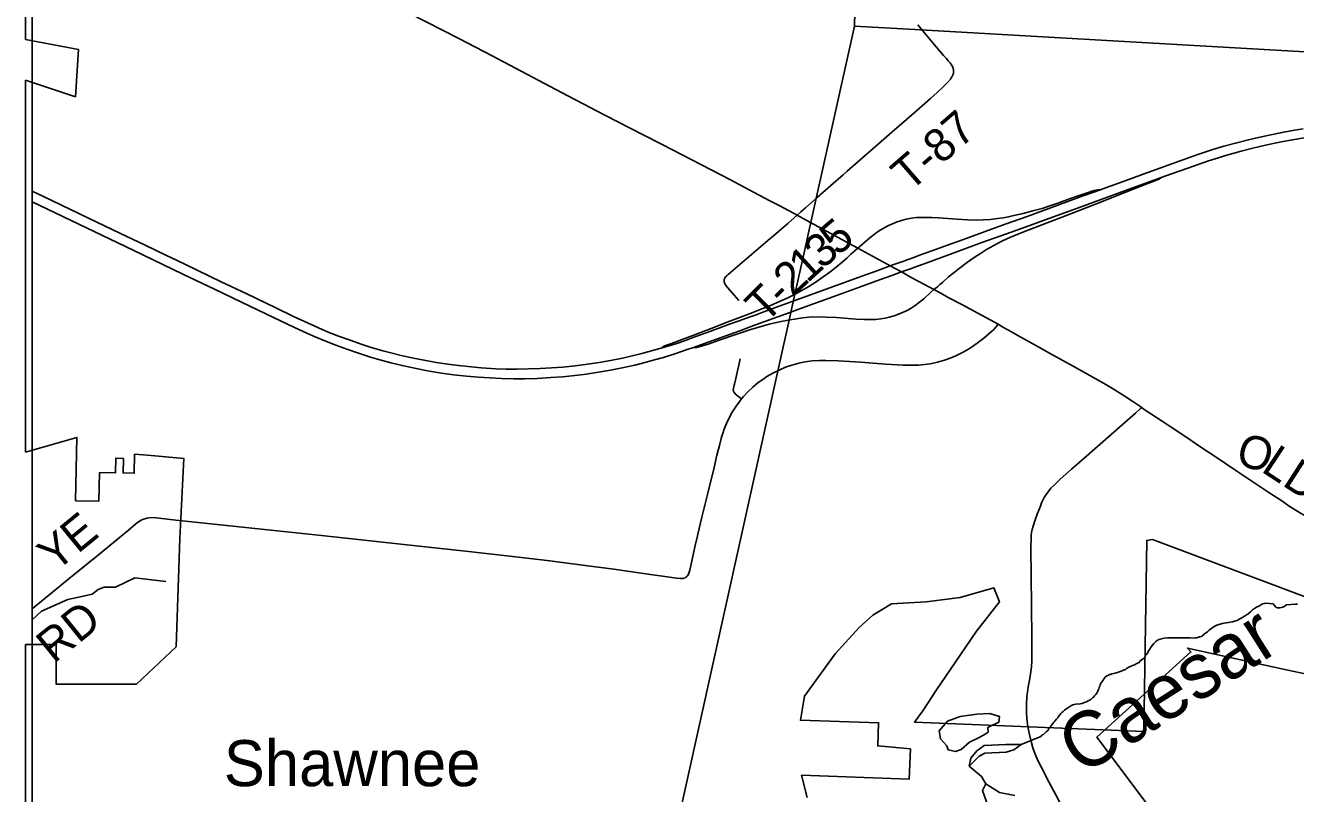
# Model space of a CAD drawing. Extents: x -5.4 to 49.9, y 13.2 to 48.4.
# Drawn here: x 26.266 to 28.445, y 43.526 to 44.845 of the extents above; entities that cross this region are included whole.
import ezdxf

# ---------------------------------------------------------------- set-up
doc = ezdxf.new("R2010")
doc.units = 0
for name, color, linetype in [('GM_X_Corporation', 7, 'Continuous'), ('GM_X_County_Road', 7, 'Continuous'), ('GM_X_County_Road_Text', 7, 'Continuous'), ('GM_X_Interchange_Ramps', 7, 'Continuous'), ('GM_X_Major_Lake', 7, 'Continuous'), ('GM_X_Major_River', 7, 'Continuous'), ('GM_X_Major_River_Text', 7, 'Continuous'), ('GM_X_Minor_Lake', 7, 'Continuous'), ('GM_X_Minor_River', 7, 'Continuous'), ('GM_X_Township', 7, 'Continuous'), ('GM_X_Township_Road', 7, 'Continuous'), ('GM_X_Township_Road_Text', 7, 'Continuous'), ('GM_X_Unincorporated_Text', 7, 'Continuous'), ('GM_X_US_Route', 7, 'Continuous')]:
    doc.layers.add(name, color=color, linetype=linetype)

msp = doc.modelspace()

# ---------------------------------------------------------------- linework, layer by layer
at = {"layer": 'GM_X_Corporation'}
for p, q in [((26.2655, 44.9666), (26.2655, 44.8206)), ((26.2655, 44.7507), (26.2655, 44.1125)), ((26.2655, 43.7825), (26.2655, 42.0542))]:
    msp.add_line(p, q, dxfattribs=at)
for points in [[(26.2655, 44.8206), (26.3566, 44.8036), (26.3514, 44.7225), (26.2655, 44.7507)], [(26.2655, 44.1125), (26.354, 44.1377), (26.3517, 44.0289), (26.3915, 44.0281), (26.3925, 44.0775), (26.42, 44.0769), (26.4205, 44.1021), (26.4337, 44.1015), (26.4332, 44.0767), (26.4522, 44.0763), (26.4528, 44.1087), (26.4815, 44.1066), (26.5373, 44.1017), (26.5303, 43.9641), (26.5283, 43.896), (26.524, 43.7782), (26.4559, 43.714), (26.3185, 43.714), (26.3185, 43.7825), (26.2655, 43.7825)], [(27.607, 43.5196), (27.5973, 43.558), (27.7819, 43.5513), (27.784, 43.6031), (27.7279, 43.6084), (27.7293, 43.6479), (27.5954, 43.6522), (27.6024, 43.6936), (27.6548, 43.7665), (27.6959, 43.8117), (27.7194, 43.8326), (27.7513, 43.8519), (27.8109, 43.8557), (27.8694, 43.8629), (27.9272, 43.8793), (27.9368, 43.8557), (27.8973, 43.805), (27.8693, 43.7642), (27.8286, 43.7043), (27.8052, 43.6682), (27.7912, 43.6491), (28.1844, 43.6332), (28.1896, 43.961), (28.1991, 43.9624), (28.4932, 43.852)], [(28.4935, 43.3784), (28.4313, 43.404), (28.3949, 43.0628), (28.0147, 43.1011), (28.0164, 43.1218), (28.0232, 43.1917), (28.0637, 43.1878), (28.081, 43.3697), (28.1405, 43.3662), (28.1461, 43.4292), (28.1296, 43.4307), (28.1348, 43.4852), (28.2128, 43.4782), (28.2091, 43.4829), (28.104, 43.6235), (28.2652, 43.7695), (28.2592, 43.7763), (28.4317, 43.7385), (28.475, 43.729)]]:
    msp.add_lwpolyline(points, dxfattribs=at)
at = {"layer": 'GM_X_County_Road'}
for points in [[(26.8947, 44.8808), (26.925, 44.8655), (27.009, 44.8225), (27.0663, 44.7925), (27.196, 44.7242), (27.2235, 44.7097), (27.2445, 44.6989), (27.2809, 44.68), (27.3256, 44.6569), (27.3583, 44.6402), (27.4753, 44.5798), (27.506, 44.5634), (27.543, 44.544)], [(27.543, 44.544), (27.5533, 44.5386), (27.5598, 44.5351)], [(27.5598, 44.5351), (27.5897, 44.5192)], [(27.5897, 44.5192), (27.6054, 44.5106), (27.6399, 44.4918), (27.6788, 44.4706), (27.6939, 44.4627)], [(27.6939, 44.4627), (27.7252, 44.4454), (27.7495, 44.4321), (27.7687, 44.4217), (27.7867, 44.4118), (27.8079, 44.4003), (27.8244, 44.3913)], [(27.8244, 44.3913), (27.8361, 44.385), (27.8489, 44.378), (27.872, 44.3656), (27.9343, 44.3318)], [(27.9343, 44.3318), (27.9424, 44.3272), (27.951, 44.3225), (27.9736, 44.3098), (27.9887, 44.3013), (28.0001, 44.2949), (28.0268, 44.28)], [(28.0268, 44.28), (28.0343, 44.2759), (28.063, 44.2599), (28.1012, 44.239), (28.119, 44.2288), (28.1338, 44.2197), (28.1506, 44.209), (28.1657, 44.1992), (28.1808, 44.189)], [(27.9918, 43.842), (27.9917, 43.8506), (27.9911, 43.8985), (27.9908, 43.9501), (27.9912, 43.9637), (27.9914, 43.9699), (27.992, 43.9747), (27.993, 43.9796), (27.9947, 43.9855), (27.998, 43.9961), (28.0016, 44.0061), (28.007, 44.02), (28.0091, 44.0253), (28.0118, 44.0309), (28.0136, 44.0345), (28.0157, 44.0383), (28.0186, 44.0423), (28.022, 44.0468), (28.0251, 44.0505), (28.03, 44.0552), (28.0411, 44.066), (28.0606, 44.0831), (28.0817, 44.1016), (28.1475, 44.1595), (28.1699, 44.1793), (28.179, 44.1874), (28.1808, 44.189)], [(28.1808, 44.189), (28.1852, 44.1859), (28.2157, 44.1656), (28.2282, 44.1574), (28.258, 44.1373), (28.2747, 44.1264), (28.2876, 44.1178), (28.3066, 44.1051), (28.3421, 44.0812), (28.3992, 44.0433), (28.4212, 44.0287), (28.4273, 44.0244), (28.434, 44.02), (28.4398, 44.0163), (28.4533, 44.0077), (28.4613, 44.0029), (28.4753, 43.995), (28.4933, 43.9852), (28.5266, 43.9671), (28.5415, 43.9591)], [(27.9838, 43.6938), (27.9847, 43.7003), (27.986, 43.7095), (27.9888, 43.7241), (27.9906, 43.7358), (27.9915, 43.7439), (27.9921, 43.7538), (27.9924, 43.7619), (27.9924, 43.7688), (27.9925, 43.8003), (27.9918, 43.842)], [(28.0483, 43.4917), (28.0473, 43.4956), (28.0453, 43.5009), (28.0407, 43.5099), (28.0339, 43.5231), (28.022, 43.5457), (28.0088, 43.571), (28.0023, 43.5844), (27.9982, 43.5941), (27.9943, 43.6051), (27.9904, 43.6182), (27.9875, 43.6302), (27.9855, 43.6418), (27.9839, 43.6547), (27.983, 43.667), (27.9829, 43.6788), (27.9837, 43.693), (27.9838, 43.6938)]]:
    msp.add_lwpolyline(points, dxfattribs=at)
at = {"layer": 'GM_X_Interchange_Ramps'}
for points in [[(27.8244, 44.3913), (27.8302, 44.3964), (27.8344, 44.4), (27.8394, 44.4043), (27.8494, 44.4132), (27.8568, 44.4193), (27.8676, 44.4277), (27.8821, 44.4384), (27.8933, 44.4463), (27.9042, 44.4535), (27.9148, 44.46), (27.9272, 44.4671), (27.9399, 44.4737), (27.9505, 44.4789), (27.9612, 44.4838), (27.9768, 44.4902), (28.011, 44.5033), (28.05, 44.5182), (28.1015, 44.5383), (28.1517, 44.5578), (28.1735, 44.5664), (28.1987, 44.5762), (28.2093, 44.5803), (28.2109, 44.5811), (28.2141, 44.5835)], [(28.1101, 44.5629), (28.1053, 44.5625), (28.1026, 44.5623), (28.0992, 44.5615), (28.0955, 44.5604), (28.0908, 44.5588), (28.0737, 44.5531), (28.0567, 44.5469), (28.037, 44.5396), (28.0252, 44.5355), (28.0098, 44.5308), (27.9942, 44.5264), (27.9773, 44.5222), (27.9613, 44.5183), (27.9522, 44.5164), (27.9433, 44.5148), (27.9333, 44.5132), (27.9212, 44.5118), (27.9087, 44.5109), (27.8987, 44.5105), (27.882, 44.511), (27.864, 44.512), (27.8324, 44.5144), (27.82, 44.5151), (27.81, 44.5154), (27.8001, 44.5153), (27.7939, 44.5149), (27.7859, 44.5139), (27.7767, 44.5121), (27.7689, 44.5101), (27.7612, 44.5076), (27.7531, 44.5044), (27.7452, 44.5007), (27.7381, 44.497), (27.7312, 44.4928), (27.7245, 44.4883), (27.7171, 44.4826), (27.7104, 44.477), (27.6939, 44.4627)], [(27.6939, 44.4627), (27.6897, 44.4591), (27.6818, 44.4522), (27.6752, 44.4457), (27.6668, 44.4383), (27.6568, 44.43), (27.6455, 44.4213), (27.6344, 44.4132), (27.6221, 44.4049), (27.6095, 44.3969), (27.5977, 44.39), (27.5851, 44.3832), (27.5723, 44.3768), (27.5605, 44.3714), (27.5428, 44.3638), (27.5232, 44.356), (27.5106, 44.3511), (27.4652, 44.3336), (27.4496, 44.3276), (27.4153, 44.3144), (27.3926, 44.3058), (27.3757, 44.2997), (27.3654, 44.2962), (27.3626, 44.295), (27.3604, 44.2939), (27.3592, 44.2929), (27.3583, 44.2915)], [(27.4119, 44.2922), (27.415, 44.2918), (27.4171, 44.292), (27.4192, 44.2924), (27.437, 44.298), (27.4559, 44.3044), (27.4846, 44.3146), (27.5033, 44.3209), (27.5064, 44.3219), (27.5237, 44.3271), (27.5417, 44.3319), (27.5592, 44.336), (27.5745, 44.3391), (27.5886, 44.3414), (27.5991, 44.3428), (27.6102, 44.3438), (27.6239, 44.3444), (27.6394, 44.3443), (27.6574, 44.3433), (27.6909, 44.3406), (27.7046, 44.34), (27.7145, 44.3399), (27.7238, 44.3403), (27.7331, 44.3412), (27.7405, 44.3423), (27.7478, 44.3439), (27.7561, 44.3462), (27.7637, 44.349), (27.7706, 44.3519), (27.7784, 44.3558), (27.7854, 44.3598), (27.7922, 44.3642), (27.7997, 44.3698), (27.8068, 44.3758), (27.818, 44.3857), (27.8244, 44.3913)]]:
    msp.add_lwpolyline(points, dxfattribs=at)
at = {"layer": 'GM_X_Major_Lake'}
msp.add_lwpolyline([(27.9634, 43.5234), (27.937, 43.5286), (27.9134, 43.5431), (27.9079, 43.5315), (27.916, 43.5078)], dxfattribs=at)
at = {"layer": 'GM_X_Major_River'}
for points in [[(28.2412, 43.794), (28.2435, 43.7939), (28.2511, 43.7939), (28.2575, 43.7938), (28.264, 43.7937), (28.2689, 43.7933), (28.2727, 43.7936), (28.275, 43.7936), (28.2799, 43.7955), (28.2834, 43.7962), (28.288, 43.7999), (28.291, 43.8026), (28.2937, 43.8041), (28.2964, 43.8067), (28.2987, 43.8086), (28.3014, 43.8104), (28.3052, 43.8131), (28.3075, 43.8142), (28.3098, 43.8153), (28.3132, 43.8168), (28.3193, 43.8186), (28.3257, 43.8197), (28.3299, 43.82), (28.3326, 43.8207), (28.3364, 43.8215), (28.3398, 43.8222), (28.3425, 43.8229), (28.3444, 43.8237), (28.3463, 43.8248), (28.3493, 43.8263), (28.3524, 43.8281), (28.357, 43.8311), (28.3604, 43.833), (28.3631, 43.8345), (28.3673, 43.8386), (28.3708, 43.8416), (28.3746, 43.8442), (28.378, 43.8465), (28.3807, 43.8476), (28.3845, 43.8498), (28.3883, 43.8521), (28.3914, 43.8528), (28.3948, 43.8531), (28.4001, 43.8527), (28.4062, 43.8519), (28.4084, 43.8492), (28.411, 43.8465), (28.4137, 43.845), (28.4178, 43.8453), (28.4205, 43.846), (28.4232, 43.8464), (28.4255, 43.8475), (28.4274, 43.849), (28.4293, 43.8505), (28.4445, 43.8515), (28.4479, 43.8518)], [(27.9741, 43.6105), (28.0076, 43.6247), (28.0102, 43.627), (28.0122, 43.6281), (28.0145, 43.63), (28.0171, 43.6326), (28.0198, 43.6345), (28.021, 43.6371), (28.0229, 43.6401), (28.0248, 43.6424), (28.0267, 43.6443), (28.0287, 43.6473), (28.0302, 43.6492), (28.0318, 43.651), (28.0344, 43.6541), (28.0367, 43.6567), (28.0383, 43.659), (28.0402, 43.6616), (28.0421, 43.6639), (28.0441, 43.6661), (28.0463, 43.6676), (28.0486, 43.6699), (28.0521, 43.6725), (28.054, 43.6736), (28.0574, 43.6758), (28.0593, 43.677), (28.0628, 43.6785), (28.0651, 43.6792), (28.0677, 43.6799), (28.0704, 43.6803), (28.0727, 43.6802), (28.0753, 43.6806), (28.0787, 43.6813), (28.0841, 43.6832), (28.086, 43.6839), (28.089, 43.6854), (28.0913, 43.6869), (28.0932, 43.6876), (28.0963, 43.6906), (28.0982, 43.6921), (28.0998, 43.694), (28.1024, 43.6963), (28.1044, 43.7001), (28.1055, 43.7023), (28.1063, 43.7042), (28.1071, 43.7061), (28.1079, 43.7088), (28.109, 43.711), (28.1094, 43.7129), (28.1102, 43.7148), (28.1114, 43.7167), (28.1129, 43.7186), (28.1145, 43.7212), (28.1164, 43.7242), (28.1183, 43.7261), (28.121, 43.7284), (28.1237, 43.7295), (28.1256, 43.7306), (28.1275, 43.731), (28.1298, 43.7317), (28.1328, 43.7328), (28.1355, 43.7332), (28.1393, 43.7343), (28.1419, 43.7354), (28.1454, 43.7368), (28.1484, 43.7376), (28.1503, 43.7387), (28.1522, 43.7391), (28.1549, 43.7413), (28.1587, 43.7435), (28.1625, 43.745), (28.1652, 43.7461), (28.1675, 43.7469), (28.1736, 43.7502), (28.1766, 43.7513), (28.1778, 43.7536), (28.182, 43.7574), (28.1843, 43.7585), (28.1862, 43.7604), (28.1866, 43.7626), (28.1885, 43.7649), (28.1905, 43.7668), (28.192, 43.7702), (28.1943, 43.7739), (28.197, 43.7781), (28.1993, 43.7811), (28.2016, 43.7841), (28.2039, 43.7864), (28.2055, 43.7883), (28.2089, 43.7901), (28.2123, 43.7912), (28.215, 43.7923), (28.2192, 43.7931), (28.2249, 43.7938), (28.231, 43.7937), (28.2359, 43.7936), (28.2393, 43.7936), (28.2412, 43.794)], [(27.8849, 43.5737), (27.8879, 43.587), (27.898, 43.6), (27.9103, 43.6089), (27.9479, 43.6107), (27.9741, 43.6105)], [(27.8849, 43.5737), (27.902, 43.5904), (27.9116, 43.5959), (27.9484, 43.5978), (27.9614, 43.6013), (27.9741, 43.6105)], [(27.8849, 43.5737), (27.9057, 43.5558), (27.9135, 43.5431)]]:
    msp.add_lwpolyline(points, dxfattribs=at)
at = {"layer": 'GM_X_Minor_Lake'}
for points in [[(27.8852, 43.6146), (27.8997, 43.6216), (27.9108, 43.6275), (27.9173, 43.6316), (27.9171, 43.6399), (27.9358, 43.6488), (27.9367, 43.659), (27.9201, 43.6638), (27.8981, 43.663), (27.8692, 43.6589), (27.8479, 43.6505), (27.8336, 43.634), (27.8356, 43.6203), (27.8465, 43.6084), (27.849, 43.6015), (27.8615, 43.5986), (27.871, 43.6019)], [(27.8709, 43.6019), (27.8852, 43.6146)]]:
    msp.add_lwpolyline(points, dxfattribs=at)
at = {"layer": 'GM_X_Minor_River'}
msp.add_lwpolyline([(26.2771, 43.8248), (26.293, 43.8396), (26.3381, 43.8598), (26.3677, 43.8658), (26.3799, 43.8687), (26.3903, 43.8769), (26.4006, 43.8805), (26.4203, 43.8806), (26.4535, 43.8968), (26.5065, 43.8906)], dxfattribs=at)
at = {"layer": 'GM_X_Township'}
msp.add_line((26.2771, 45.1783), (26.2771, 40.9761), dxfattribs=at)
for points in [[(28.0105, 47.4437), (27.6877, 47.1657), (27.6499, 47.1327), (27.6308, 47.1161), (28.089, 46.5424), (27.3995, 45.9845), (27.4216, 45.9826), (27.5161, 45.979), (27.573, 45.9769), (27.6274, 45.9769), (27.7195, 46.0028), (27.6935, 45.0509), (27.691, 44.9621), (27.6878, 44.8437), (27.7914, 44.8377), (29.42, 44.7443), (29.8881, 44.7175), (31.3945, 44.5822), (32.3292, 44.4982), (33.0771, 44.431)], [(27.3776, 43.4437), (27.5584, 44.2595), (27.5771, 44.344), (27.5806, 44.36), (27.5858, 44.3833), (27.6011, 44.4523), (27.6103, 44.4939), (27.6878, 44.8437), (27.691, 44.9621)], [(29.42, 44.7443), (27.7914, 44.8377), (27.6878, 44.8437), (27.6103, 44.4939), (27.6011, 44.4523), (27.5858, 44.3833), (27.5806, 44.36), (27.5771, 44.344), (27.5584, 44.2595), (27.3776, 43.4437)]]:
    msp.add_lwpolyline(points, dxfattribs=at)
at = {"layer": 'GM_X_Township_Road'}
for points in [[(27.6686, 44.5886), (27.6755, 44.5946), (27.7245, 44.6377), (27.7474, 44.6577), (27.7944, 44.6984), (27.8184, 44.7192), (27.8299, 44.7296), (27.8407, 44.74), (27.8477, 44.7471), (27.8526, 44.7527), (27.8539, 44.7547), (27.855, 44.7564), (27.8559, 44.7578), (27.8565, 44.759), (27.8569, 44.76), (27.8574, 44.7612), (27.8577, 44.7624), (27.8579, 44.7639), (27.858, 44.7651), (27.858, 44.7663), (27.8579, 44.7676), (27.8578, 44.769), (27.8576, 44.7704), (27.8572, 44.7716), (27.8568, 44.7727), (27.8562, 44.774), (27.8551, 44.7761), (27.8541, 44.7775), (27.8531, 44.7788), (27.852, 44.7804), (27.8505, 44.7822), (27.8489, 44.784), (27.8457, 44.7878), (27.8408, 44.7934), (27.8218, 44.8156), (27.8024, 44.8391), (27.7968, 44.846)], [(27.5897, 44.5192), (27.5961, 44.5249), (27.6039, 44.532), (27.624, 44.5496), (27.6474, 44.5701), (27.6686, 44.5886)], [(27.5434, 44.4791), (27.5448, 44.4803), (27.5618, 44.4948), (27.5735, 44.505), (27.5897, 44.5192)], [(27.4895, 44.3729), (27.4815, 44.3819), (27.4706, 44.3946), (27.4675, 44.3986), (27.4668, 44.3996), (27.4663, 44.4004), (27.4655, 44.4019), (27.4651, 44.4029), (27.4647, 44.4038), (27.4646, 44.4047), (27.4644, 44.4059), (27.4644, 44.4069), (27.4645, 44.4078), (27.4647, 44.409), (27.465, 44.41), (27.4653, 44.4108), (27.4658, 44.4117), (27.4663, 44.4125), (27.4672, 44.4135), (27.4679, 44.4144), (27.4693, 44.4157), (27.4711, 44.4173), (27.4835, 44.4278), (27.4996, 44.4414), (27.5434, 44.4791)], [(27.8701, 44.2816), (27.8736, 44.2833), (27.8838, 44.2891), (27.8905, 44.2935), (27.8986, 44.2993), (27.9097, 44.3082), (27.923, 44.3194), (27.927, 44.3232), (27.9303, 44.3268), (27.9343, 44.3318)], [(27.48, 44.2185), (27.4804, 44.2223), (27.4816, 44.2272), (27.482, 44.2291), (27.4842, 44.2387), (27.4874, 44.2522), (27.4896, 44.2617), (27.4917, 44.2726)], [(27.4944, 44.2038), (27.4976, 44.2077), (27.5052, 44.2159), (27.5139, 44.2241), (27.523, 44.2317), (27.5305, 44.2373), (27.5378, 44.2421), (27.5481, 44.248), (27.5587, 44.2534), (27.5696, 44.258), (27.5808, 44.2618), (27.5923, 44.265), (27.6033, 44.2673), (27.6156, 44.269), (27.6281, 44.2698), (27.6387, 44.2698), (27.6599, 44.2691), (27.699, 44.2666), (27.7411, 44.2636), (27.7715, 44.2618), (27.787, 44.2615), (27.7981, 44.2618), (27.808, 44.2627), (27.8184, 44.2642), (27.8304, 44.2667), (27.8423, 44.2701), (27.8523, 44.2735), (27.862, 44.2776), (27.8701, 44.2816)], [(27.4631, 44.1476), (27.4641, 44.1509), (27.4684, 44.1614), (27.4732, 44.1715), (27.4783, 44.1808), (27.485, 44.1914), (27.4912, 44.2), (27.4944, 44.2038)], [(27.4944, 44.2038), (27.4848, 44.211), (27.4817, 44.2147), (27.48, 44.2185)], [(27.4521, 44.107), (27.4556, 44.1216), (27.4595, 44.1361)], [(27.4595, 44.1361), (27.4605, 44.1397), (27.4631, 44.1476)], [(27.4217, 43.9815), (27.4262, 44.0009), (27.4363, 44.0419), (27.447, 44.086), (27.4521, 44.107)], [(26.2771, 43.8438), (26.3404, 43.8953), (26.3911, 43.9364), (26.4423, 43.9788), (26.4552, 43.9896), (26.4598, 43.9929), (26.4653, 43.9961), (26.468, 43.9973), (26.4706, 43.9982), (26.4739, 43.9991), (26.4774, 43.9997), (26.485, 44), (26.495, 43.9993), (26.5234, 43.9959), (26.6272, 43.9848), (26.6865, 43.9785), (26.7737, 43.9691), (26.9096, 43.9544), (27.0208, 43.9424), (27.0918, 43.9346), (27.1609, 43.9263), (27.2257, 43.9181), (27.275, 43.9115), (27.3223, 43.9047), (27.3826, 43.8961), (27.3893, 43.8954), (27.3935, 43.8956), (27.3953, 43.896), (27.3974, 43.8968), (27.3989, 43.8979), (27.4004, 43.8992), (27.4014, 43.9004)], [(27.4188, 43.9688), (27.4195, 43.9718), (27.4217, 43.9815)], [(27.4014, 43.9004), (27.403, 43.9031), (27.4042, 43.9063), (27.4053, 43.9099), (27.4065, 43.9148), (27.4149, 43.9524), (27.4188, 43.9688)]]:
    msp.add_lwpolyline(points, dxfattribs=at)
at = {"layer": 'GM_X_US_Route'}
for points in [[(26.2771, 44.5605), (26.2976, 44.5505), (26.3106, 44.5444), (26.3273, 44.5362), (26.357, 44.522), (26.375, 44.5134), (26.4276, 44.4882), (26.4709, 44.4677), (26.5067, 44.4505), (26.5269, 44.4408), (26.5392, 44.4349), (26.5811, 44.4146), (26.6013, 44.4049), (26.6457, 44.3839), (26.6938, 44.3607), (26.7257, 44.3452), (26.7493, 44.3341), (26.7749, 44.3228), (26.7881, 44.3174), (26.8044, 44.3111), (26.8225, 44.3045), (26.8431, 44.2974), (26.8573, 44.2928), (26.8788, 44.2865), (26.8926, 44.2828), (26.9101, 44.2785), (26.9314, 44.2738), (26.9497, 44.2701), (26.9705, 44.2664), (26.9902, 44.2633), (27.0087, 44.2609), (27.0309, 44.2586), (27.0477, 44.2572), (27.0731, 44.2557), (27.0905, 44.2551), (27.1086, 44.2549), (27.1285, 44.2552), (27.149, 44.2559), (27.1683, 44.2569), (27.1875, 44.2584), (27.2085, 44.2606), (27.2301, 44.2633), (27.2498, 44.2664), (27.2694, 44.2698), (27.2901, 44.2739), (27.3041, 44.2771), (27.3234, 44.2818), (27.3438, 44.2873), (27.3583, 44.2915), (27.3659, 44.2938), (27.3814, 44.2986), (27.3961, 44.3036), (27.4142, 44.3101), (27.4353, 44.3178), (27.4738, 44.3318), (27.4884, 44.337), (27.509, 44.3445), (27.5194, 44.3483), (27.5281, 44.3515), (27.5526, 44.3605), (27.6145, 44.383), (27.7068, 44.4166), (27.7237, 44.4227), (27.7495, 44.4321), (27.7541, 44.4338), (27.7693, 44.4392), (27.788, 44.4459), (27.8014, 44.4509), (27.8207, 44.4578), (27.8476, 44.4675), (27.8732, 44.477), (27.9229, 44.4951), (27.948, 44.5041), (27.9843, 44.5171), (28.0788, 44.5516), (28.097, 44.5581), (28.1101, 44.5629), (28.1139, 44.5643), (28.1572, 44.5798), (28.1899, 44.5918), (28.2137, 44.6006), (28.2389, 44.6097), (28.277, 44.6231), (28.3029, 44.6317), (28.3219, 44.6374), (28.3416, 44.6429), (28.3639, 44.6486), (28.376, 44.6515), (28.3996, 44.6567), (28.4246, 44.6618), (28.4429, 44.6651), (28.4576, 44.6675)], [(27.7856, 44.4278), (27.79, 44.4294), (27.8139, 44.4381), (27.8571, 44.4539), (27.9067, 44.4721), (27.9488, 44.4872), (27.9727, 44.4959), (27.9996, 44.5056), (28.0154, 44.5114), (28.0767, 44.5337), (28.1637, 44.5652), (28.2141, 44.5835), (28.2222, 44.5864), (28.2696, 44.6033), (28.2955, 44.6122), (28.3126, 44.6177), (28.3227, 44.6208), (28.3515, 44.6289), (28.3713, 44.634), (28.3931, 44.6391), (28.4199, 44.6448), (28.4395, 44.6485), (28.4628, 44.6524)], [(26.2771, 44.5421), (26.3837, 44.4909), (26.4504, 44.4589), (26.5355, 44.4181), (26.5898, 44.3919), (26.6363, 44.3696), (26.6913, 44.3434), (26.726, 44.3268), (26.7497, 44.3158), (26.7628, 44.3101), (26.7794, 44.3032), (26.7979, 44.296), (26.8171, 44.289), (26.8371, 44.2822), (26.8578, 44.2756), (26.8739, 44.2709), (26.8925, 44.2658), (26.9118, 44.2611), (26.936, 44.2558), (26.9555, 44.2521), (26.9794, 44.2482), (27.0003, 44.2454), (27.0226, 44.2429), (27.043, 44.2411), (27.0622, 44.2398), (27.0826, 44.2388), (27.1037, 44.2384), (27.1223, 44.2385), (27.1434, 44.2391), (27.167, 44.2403), (27.1868, 44.2419), (27.2035, 44.2436), (27.2275, 44.2465), (27.249, 44.2497), (27.2692, 44.2531), (27.2893, 44.2571), (27.3111, 44.2619), (27.3304, 44.2667), (27.3447, 44.2706), (27.3602, 44.2751), (27.3798, 44.2813), (27.401, 44.2884), (27.4119, 44.2922), (27.4308, 44.2989), (27.4974, 44.3232), (27.5045, 44.3259), (27.5201, 44.3316), (27.571, 44.3499), (27.5972, 44.3595), (27.6591, 44.382), (27.6901, 44.3933), (27.731, 44.4081), (27.752, 44.4157), (27.7687, 44.4217), (27.7856, 44.4278)]]:
    msp.add_lwpolyline(points, dxfattribs=at)

# ---------------------------------------------------------------- texts
at = {"layer": 'GM_X_County_Road_Text'}
for s, rotation, p in [('O', 343.9065, (28.34, 44.0923)), ('L', 326.5108, (28.3839, 44.0804)), ('D', 327.1928, (28.42, 44.0565))]:
    msp.add_text(s, height=0.0568, rotation=rotation, dxfattribs=at).set_placement(p)
at = {"layer": 'GM_X_Major_River_Text'}
msp.add_text('Caesar', height=0.09469, rotation=32.3835, dxfattribs=at).set_placement((28.0778, 43.5558))
at = {"layer": 'GM_X_Township_Road_Text'}
for s, height, rotation, p in [('T-87', 0.05682, 40.9837, (27.7827, 44.5578)), ('5', 0.0568, 40.4139, (27.6591, 44.4477)), ('3', 0.0568, 40.9857, (27.6328, 44.4248)), ('1', 0.0568, 42.3643, (27.6072, 44.4015)), ('2', 0.0568, 43.3733, (27.582, 44.3776)), ('T', 0.0568, 44.6545, (27.5353, 44.3317)), ('-', 0.0568, 44.2825, (27.5654, 44.3615)), ('E', 0.0568, 39.2903, (26.3553, 43.937)), ('Y', 0.0568, 39.2906, (26.3166, 43.9054)), ('RD', 0.05682, 39.0466, (26.3141, 43.7484))]:
    msp.add_text(s, height=height, rotation=rotation, dxfattribs=at).set_placement(p)
at = {"layer": 'GM_X_Unincorporated_Text'}
msp.add_text('Shawnee', height=0.07898, rotation=0, dxfattribs=at).set_placement((26.6059, 43.5392))

doc.saveas('drawing.dxf')
